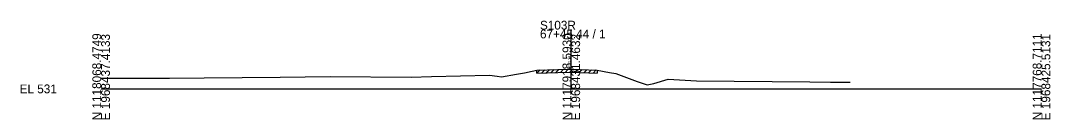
# Model space of a CAD drawing. Extents: x 974 to 1303, y 990 to 10019.
# Drawn here: x 974.3 to 1302.8, y 9490.3 to 9521.7 of the extents above; entities that cross this region are included whole.
import ezdxf

# ---------------------------------------------------------------- set-up
doc = ezdxf.new("R2010")
doc.units = 0
for name, color, linetype in [('Level 10', 7, 'Continuous'), ('Level 60', 7, 'Continuous'), ('Level 61', 7, 'Continuous'), ('Level 63', 7, 'Continuous')]:
    doc.layers.add(name, color=color, linetype=linetype)

msp = doc.modelspace()

# ---------------------------------------------------------------- linework, layer by layer
at = {"layer": 'Level 60'}
for p, q in [((1127.73, 9503.79), (1132.46, 9504.64)), ((1132.46, 9504.64), (1135.09, 9505.13)), ((1135.09, 9505.13), (1137.47, 9505.68)), ((1137.47, 9505.68), (1139.01, 9506.01)), ((1139.01, 9506.01), (1145.72, 9506.2)), ((1145.72, 9506.2), (1149.46, 9506.29)), ((1149.46, 9506.29), (1150, 9506.28)), ((1150, 9506.28), (1152.79, 9506.19)), ((1152.79, 9506.19), (1158.24, 9506.01)), ((1158.24, 9506.01), (1162.13, 9505.26)), ((1162.13, 9505.26), (1164.16, 9504.88)), ((1164.16, 9504.88), (1171.01, 9502.36)), ((1000, 9503.4), (1002.25, 9503.4)), ((1002.25, 9503.4), (1015.15, 9503.41)), ((1015.15, 9503.41), (1016.36, 9503.41)), ((1016.36, 9503.41), (1021.86, 9503.37)), ((1021.86, 9503.37), (1032.83, 9503.54)), ((1032.83, 9503.54), (1057.07, 9503.74)), ((1057.07, 9503.74), (1073.04, 9503.94)), ((1073.04, 9503.94), (1098.87, 9503.77)), ((1098.87, 9503.77), (1105.42, 9503.93)), ((1105.42, 9503.93), (1123.91, 9504.38)), ((1123.91, 9504.38), (1126.31, 9504.05)), ((1126.31, 9504.05), (1127.73, 9503.79)), ((1171.01, 9502.36), (1174.17, 9501.3)), ((1174.17, 9501.3), (1176.35, 9501.77)), ((1176.35, 9501.77), (1180.93, 9503.08)), ((1180.93, 9503.08), (1189.94, 9502.59)), ((1189.94, 9502.59), (1226.12, 9502.29)), ((1226.12, 9502.29), (1232.64, 9502.18)), ((1232.64, 9502.18), (1237.34, 9502.12)), ((1237.34, 9502.12), (1238.97, 9502.11))]:
    msp.add_line(p, q, dxfattribs=at)
at = {"layer": 'Level 61'}
for p, q in [((1139.01, 9505.01), (1140.04, 9506.04)), ((1139.01, 9505.01), (1139.01, 9506.01)), ((1139.01, 9505.01), (1145.72, 9505.2)), ((1140.51, 9505.05), (1141.54, 9506.08)), ((1142.01, 9505.09), (1143.04, 9506.12)), ((1143.51, 9505.13), (1144.54, 9506.16)), ((1145.01, 9505.18), (1146.04, 9506.21)), ((1145.72, 9505.2), (1149.46, 9505.29)), ((1146.51, 9505.22), (1147.54, 9506.24)), ((1148.01, 9505.26), (1149.04, 9506.28)), ((1149.46, 9505.29), (1150, 9505.28)), ((1149.51, 9505.29), (1150.48, 9506.26)), ((1150, 9505.28), (1152.79, 9505.19)), ((1151.01, 9505.24), (1151.98, 9506.21)), ((1152.51, 9505.19), (1153.48, 9506.16)), ((1152.79, 9505.19), (1158.24, 9505.01)), ((1154.01, 9505.15), (1154.98, 9506.12)), ((1155.51, 9505.1), (1156.48, 9506.07)), ((1157.01, 9505.05), (1157.98, 9506.02)), ((1158.24, 9506.01), (1158.24, 9505.01)), ((1158.24, 9505.01), (1158.24, 9505.01))]:
    msp.add_line(p, q, dxfattribs=at)
at = {"layer": 'Level 63'}
for p, q in [((1150, 9500), (1150, 9518.88)), ((1000, 9500), (1150, 9500)), ((1150, 9500), (1300, 9500))]:
    msp.add_line(p, q, dxfattribs=at)

# ---------------------------------------------------------------- texts
at = {"layer": 'Level 10'}
msp.add_text('537.28', height=0.9, rotation=90, dxfattribs=at).set_placement((1149.95, 9506.78))
at = {"layer": 'Level 63'}
for s, p in [('S103R', (1140, 9518.88)), ('67+45.44 / 1', (1140, 9516.08)), ('EL 531', (974, 9498.6))]:
    msp.add_text(s, height=2.8, dxfattribs=at).set_placement(p)
for s, p in [('N 1118068.4749', (1000, 9490)), ('E 1968437.4133', (1002.8, 9490)), ('N 1117918.5930', (1150, 9490)), ('E 1968431.4632', (1152.8, 9490)), ('N 1117768.7111', (1300, 9490)), ('E 1968425.5131', (1302.8, 9490))]:
    msp.add_text(s, height=2.8, rotation=90, dxfattribs=at).set_placement(p)

doc.saveas('drawing.dxf')
